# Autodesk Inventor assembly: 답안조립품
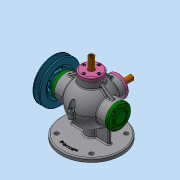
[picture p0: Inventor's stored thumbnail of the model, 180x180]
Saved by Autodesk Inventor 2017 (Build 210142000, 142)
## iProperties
Part Number: 답안조립품
Material: 일반
Document SubType Name: Assembly
Designer: MRC
Author: MRC
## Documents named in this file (17)
- C:\Users\MRC\Desktop\620909V1002\답안조립품.iam
- C:\Users\MRC\Desktop\620909V1002\본체.ipt
- C:\Users\MRC\Desktop\620909V1002\V-벨트풀리.ipt
- C:\Users\MRC\Desktop\620909V1002\너트-M8x1.ipt
- C:\Users\MRC\Desktop\620909V1002\뒤커버.ipt
- C:\Users\MRC\Desktop\620909V1002\베어링- 6202.ipt
- C:\Users\MRC\Desktop\620909V1002\본체커버.ipt
- C:\Users\MRC\Desktop\620909V1002\볼트 M4x0.7.ipt
- C:\Users\MRC\Desktop\620909V1002\슬라이드 커버.ipt
- C:\Users\MRC\Desktop\620909V1002\슬라이드.ipt
- C:\Users\MRC\Desktop\620909V1002\앞커버.ipt
- C:\Users\MRC\Desktop\620909V1002\오일실.ipt
- C:\Users\MRC\Desktop\620909V1002\와셔 8x17.ipt
- C:\Users\MRC\Desktop\620909V1002\축.ipt
- C:\Users\MRC\Desktop\620909V1002\키-4x4.ipt
- C:\Users\MRC\Desktop\620909V1002\가변스프링1.ipt
- C:\Users\MRC\Desktop\620909V1002\가변스프링2.ipt
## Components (20 placed, 4 different names)
1. V-벨트풀리:1
2. M4x0.7x12:9
3. 가변스프링1:1
4. 가변스프링2:1
5. M4x0.7x12:1
6. M4x0.7x12:3
7. M4x0.7x12:4
8. M4x0.7x12:5
9. M4x0.7x12:2
10. M4x0.7x12:6
11. M4x0.7x12:7
12. M4x0.7x12:8
13. M4x0.7x12:10
14. M4x0.7x12:12
15. M4x0.7x12:13
16. M4x0.7x12:14
17. M4x0.7x12:11
18. M4x0.7x12:15
19. M4x0.7x12:16
20. M4x0.7x12:17
